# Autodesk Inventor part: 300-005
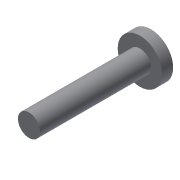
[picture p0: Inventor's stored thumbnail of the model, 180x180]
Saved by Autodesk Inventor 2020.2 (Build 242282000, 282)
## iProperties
Created: 2014-01
Part Number: 300-005
Material: Ogólny
Document SubType Name: Modeling
Designer: F.Stasiak
Density: 1 g/cm^3
Appearance: Domyślna
Manager: www.cadconsulting.pl
Company: Fabian Stasiak CAD Consulting
Author: F.Stasiak
Subject: Zbiór ćwiczeń. Autodesk Inventor 2020. Kurs podstawowy
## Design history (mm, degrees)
sketch "Szkic1"
  geometry: C1 r 5 at (0, 0); 1 further point
  constraints: 1 centre point, 1 coincident
  dimensions: "d0" = 10 diameter of C1
extrude "Wyciągnięcie proste1" new body sketch "Szkic1" distance "d1" = 50; taper "d2" = 0 deg
sketch "Szkic2"
  geometry: C1 r 5 at (0, 0) reference; C2 r 10 at (0, 0)
  constraints: 1 centre point, 1 coincident
  dimensions: "d3" = 20 diameter of C2
extrude "Wyciągnięcie proste2" join sketch "Szkic2" distance "d4" = 5; taper "d5" = 0 deg
node "Bryła1"
